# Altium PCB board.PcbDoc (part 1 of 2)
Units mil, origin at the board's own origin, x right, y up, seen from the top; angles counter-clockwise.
Board outline 3925 x 3925 mil, 2 copper layers (Top Layer, Bottom Layer); 233 components, 182 nets, 664 pads, 429 vias.
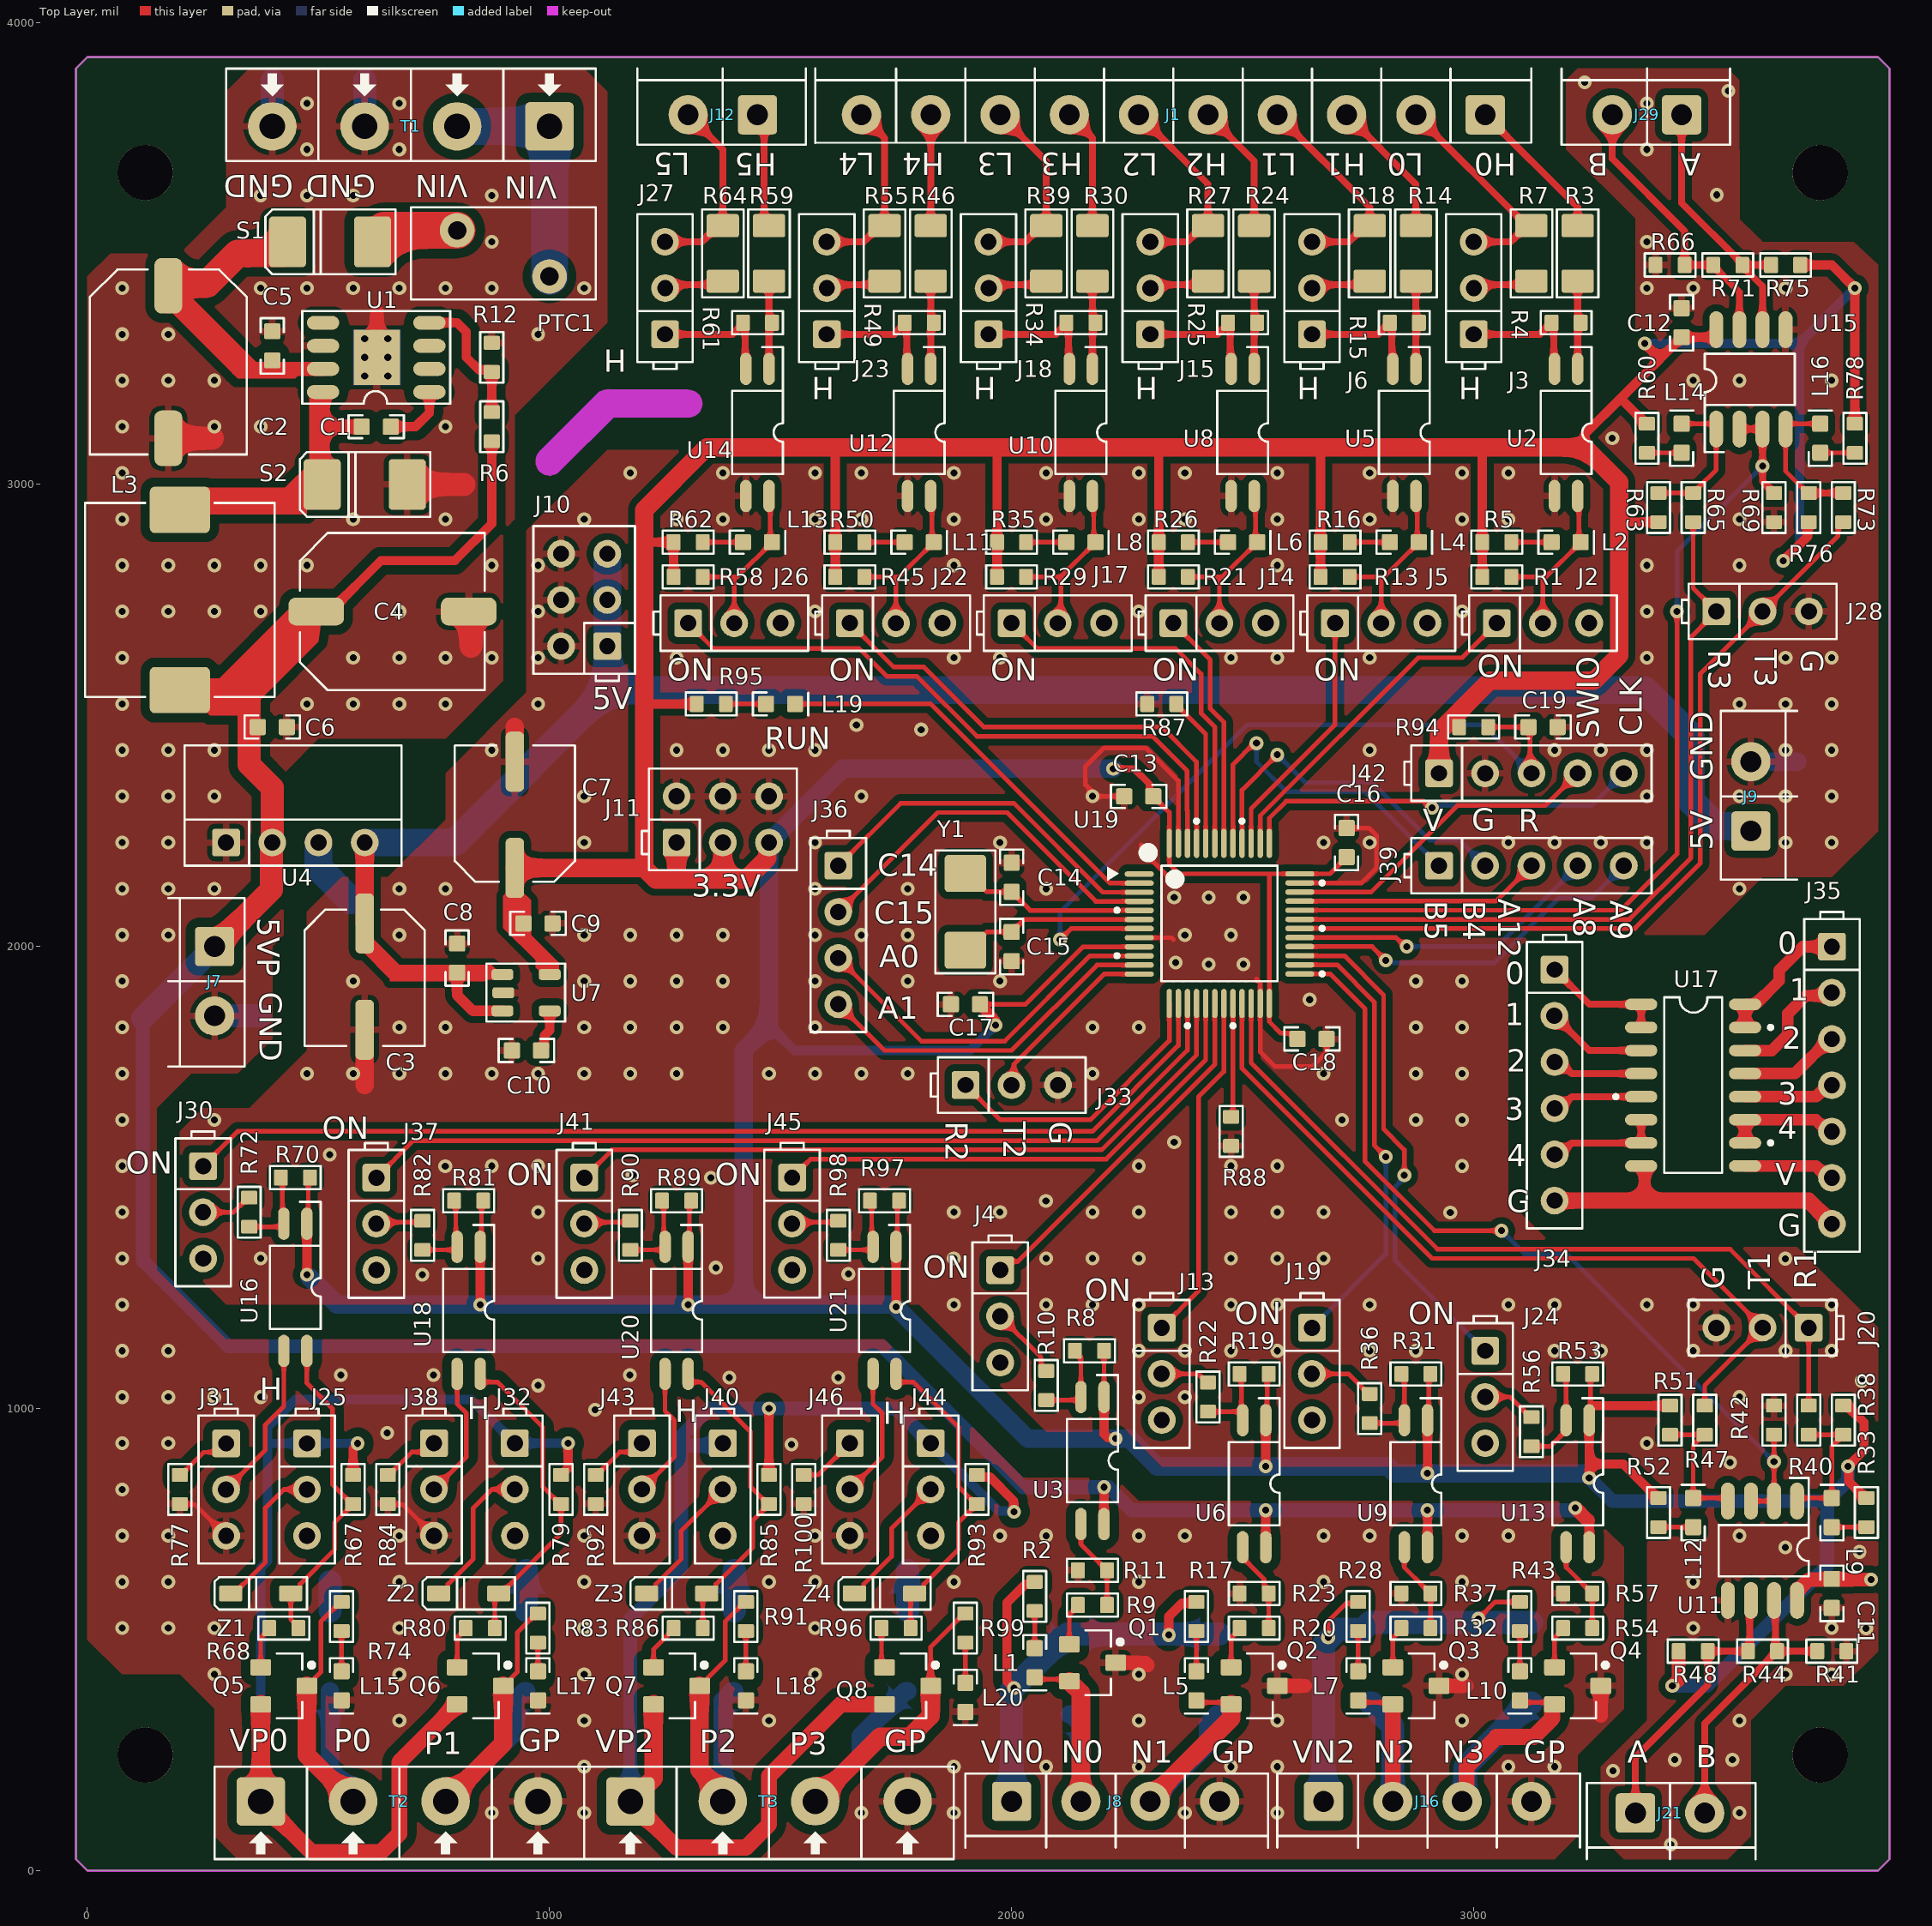
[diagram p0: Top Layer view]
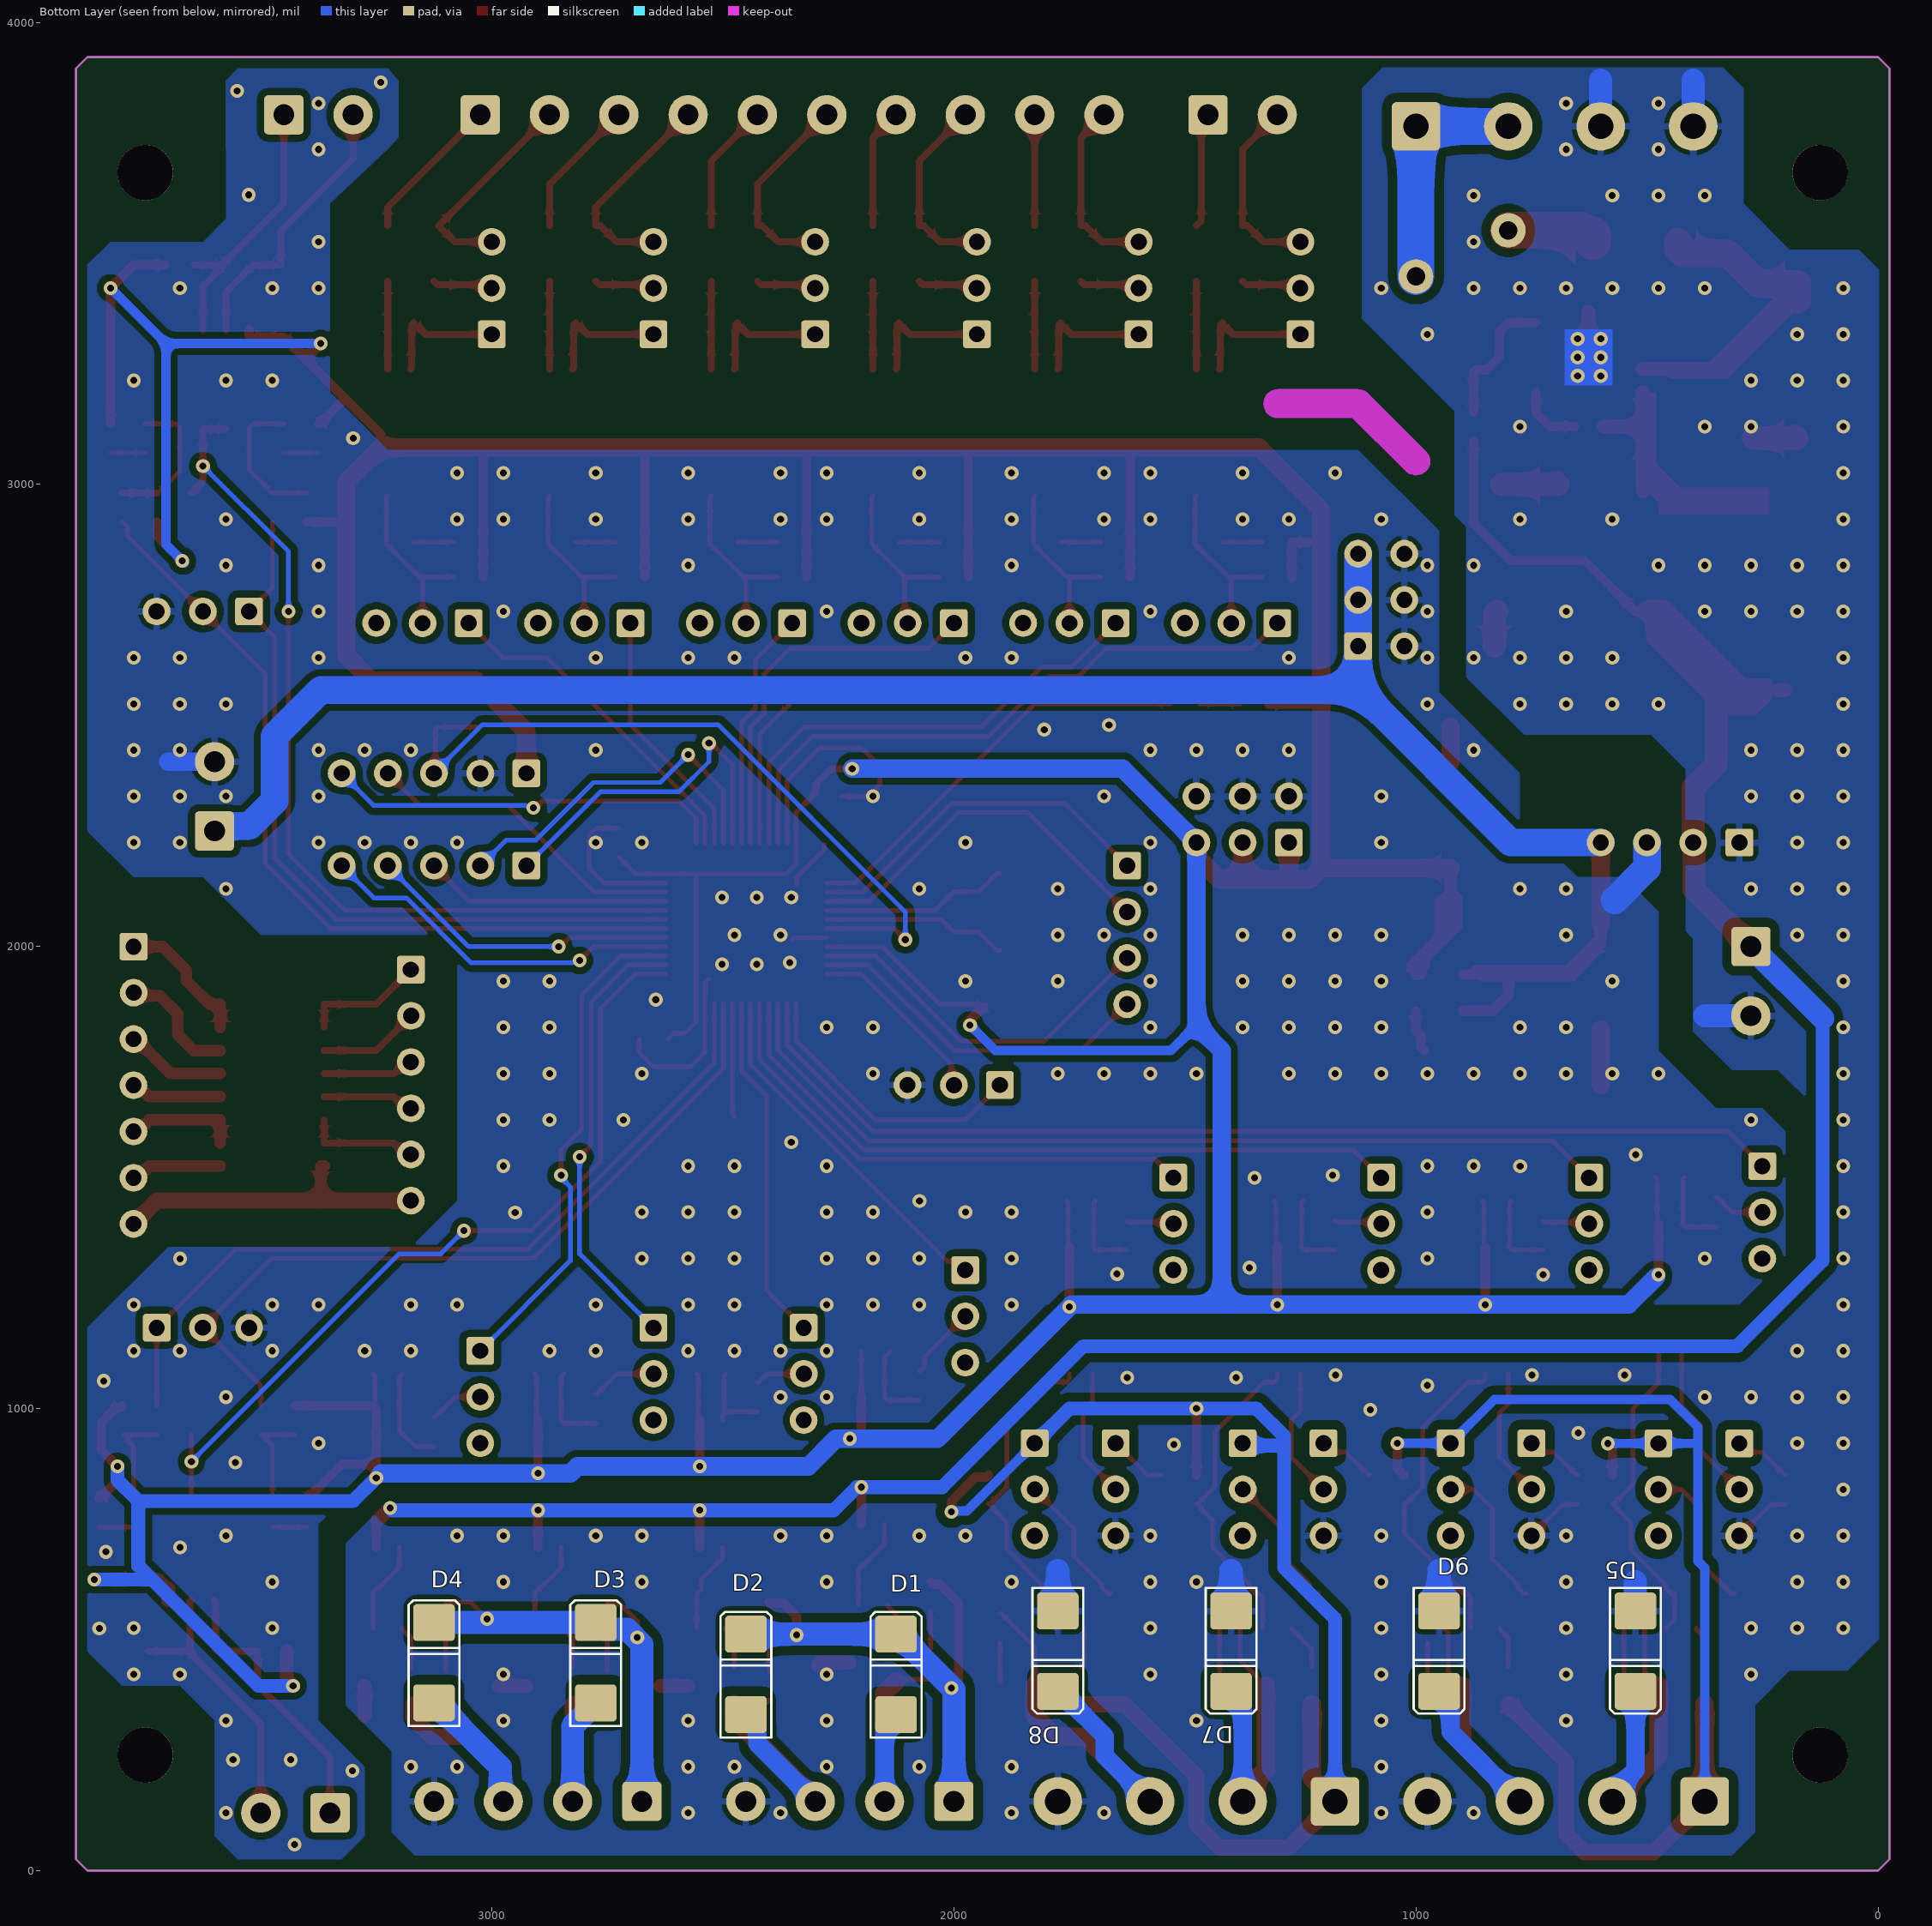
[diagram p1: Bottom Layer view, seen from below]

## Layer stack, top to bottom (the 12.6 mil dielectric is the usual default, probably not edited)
Top Solder: solder mask 0.4, Solder Resist, Dk 3.5
Top Layer: signal copper 1.4
Dielectric 1: dielectric 12.6, FR-4, Dk 4.8
Bottom Layer: signal copper 1.4
Bottom Solder: solder mask 0.4, Solder Resist, Dk 3.5

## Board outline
-25,25 0,0 3875,0 3900,25 3900,3900 3875,3925 0,3925 -25,3900
cut-out: 978.78,3071.22 ccw(c1000,3050) 1021.22,3028.78 1146.22,3153.78 ccw(c1125,3175) 1155.01,3175 ccw(c1125,3175) 1103.78,3196.22
cut-out: 1125,3144.98 cw(c1125,3175) 1125,3205.02 1300,3205.02 cw(c1300,3175) 1330.01,3175 cw(c1300,3175) 1300,3144.98

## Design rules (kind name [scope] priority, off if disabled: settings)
Clearance "Stitching GND" [IsStitchingVia and InNet('GND') vs (IsVia and (Not IsStitchingVia)) Or IsPad] p1: gap=5 ignorepadtopadclearanceinfootprint=FALSE
Clearance [InNamedPolygon('GND')] p2: gap=15 ignorepadtopadclearanceinfootprint=FALSE
Clearance "Stitching GP" [IsStitchingVia and InNet('GP') vs (IsVia and (Not IsStitchingVia)) Or IsPad] p3: gap=20 ignorepadtopadclearanceinfootprint=FALSE
Clearance Clearance_1 [InNamedPolygon('GP')] p4: gap=20 ignorepadtopadclearanceinfootprint=FALSE
Clearance Clearance_net [All] p5: gap=7 ignorepadtopadclearanceinfootprint=FALSE
HoleSize [All] p1: absolutevalues=TRUE maxlimit=150 minlimit=1 maxpercent=80.000 minpercent=20.000
HoleToHoleClearance [All] p1: gap=1 allowstackedmicrovias=TRUE
MinimumSolderMaskSliver [All] p1: minsoldermaskwidth=1
PlaneConnect [All] p1: planeconnectstyle=Relief reliefexpansion=20 reliefentries=4 reliefconductorwidth=15 reliefairgap=10
PolygonConnect PolygonConnect_1 [IsVia] p1: connectstyle=Direct reliefconductorwidth=10 reliefentries=4 polygonreliefangle="90 Angle" airgapwidth=10
PolygonConnect [All] p2: connectstyle=Relief reliefconductorwidth=15 reliefentries=4 polygonreliefangle="90 Angle" airgapwidth=10
RoutingVias [All] p1: holewidth=15 width=30 viastyle="Through Hole" minholewidth=15 minwidth=30 maxholewidth=20 maxwidth=40
SilkToSilkClearance [All] p1: silktosilkclearance=1
SilkToSolderMaskClearance [IsPad] p1: minsilkscreentomaskgap=1 clearancetoexposedcopper=TRUE
SolderMaskExpansion [All] p1: expansion=4 istentingtop=FALSE
Width [All] p1: maxlimit=100 minlimit=10 preferedwidth=30
24 further rules are at their usual default settings.

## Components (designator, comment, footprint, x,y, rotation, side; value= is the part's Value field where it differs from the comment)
C1 "10nF" "Capacitor 0603" 625,3125 r0 top value=10u
C2 "220uF/35V" "Capacitor ALU 8x10mm" 175,3100 r90 top
C3 "220uF/10V" "Capacitor ALU 6.3x7.7mm" 600,1820 r90 top
C4 "470uF/16V" "Capacitor ALU 8x10mm" 825,2725 r180 top
C5 "10nF/50V" "Capacitor 0603" 400,3300 r270 top value=10u
C6 "100nF" "Capacitor 0603" 400,2475 r180 top value=10u
C7 "220uF/10V" "Capacitor ALU 6.3x7.7mm" 925,2400 r270 top
C8 "100nF" "Capacitor 0603" 800,1975 r270 top value=10u
C9 "100nF" "Capacitor 0603" 975,2050 r180 top value=10u
C10 "22nF" "Capacitor 0603" 950,1775 r0 top value=10u
C11 "100nF" "CAPACITOR 0603" 3775,600 r90 top value=10u
C12 "100nF" "Capacitor 0603" 3450,3350 r270 top value=10u
C13 "100nF" "Capacitor 0603" 2275,2325 r180 top value=10u
C14 "22p" "Capacitor 0603" 2000,2150 r270 top value=10u
C15 "22p" "Capacitor 0603" 2000,2000 r90 top value=10u
C16 "100nF" "Capacitor 0603" 2725,2225 r270 top value=10u
C17 "100nF" "Capacitor 0603" 1900,1875 r0 top value=10u
C18 "100nF" "Capacitor 0603" 2650,1800 r0 top value=10u
C19 "100n" "Capacitor 0603" 3150,2475 r180 top value=10u
D1 "=value" "DIODE SS24 SMA" 2125,425 r90 bottom
D2 "=value" "DIODE SS24 SMA" 2450,425 r90 bottom
D3 "=value" "DIODE SS24 SMA" 2775,450 r90 bottom
D4 "=value" "DIODE SS24 SMA" 3125,450 r90 bottom
D5 "=value" "DIODE SS24 SMA" 525,475 r270 bottom
D6 "=value" "DIODE SS24 SMA" 950,475 r270 bottom
D7 "=value" "DIODE SS24 SMA" 1400,475 r270 bottom
D8 "=value" "DIODE SS24 SMA" 1775,475 r270 bottom
J1 "15EDG3.8 10P RA" "15EDG3.81 10P RA" 3025,3800 r180 top
J2 "jump 2.54mm 3p" "JUMP 2.54MM 3P" 3050,2700 r0 top
J3 "jump 2.54mm 3p" "JUMP 2.54MM 3P" 3000,3325 r90 top
J4 "jump 2.54mm 3p" "JUMP 2.54MM 3P" 1975.28,1299.69 r270 top
J5 "jump 2.54mm 3p" "JUMP 2.54MM 3P" 2700,2700 r0 top
J6 "jump 2.54mm 3p" "JUMP 2.54MM 3P" 2650,3325 r90 top
J7 "15EDG3.81 2P RA" "15EDG3.81 2P RA" 275,2000 r270 top
J8 "15EDG3.81 4P RA" "15EDG3.81 4P RA" 2000,150 r0 top
J9 "15EDG3.81 2P RA" "15EDG3.81 2P RA" 3600,2250 r90 top
J10 "jump 2.54mm 2x3p" "JUMP 2.54MM 2X3P" 1125,2650 r90 top
J11 "jump 2.54mm 2x3p" "JUMP 2.54MM 2X3P" 1275,2225 r0 top
J12 "15EDG3.81 2P RA" "15EDG3.81 2P RA" 1450,3800 r180 top
J13 "jump 2.54mm 3p" "JUMP 2.54MM 3P" 2325,1175 r270 top
J14 "jump 2.54mm 3p" "JUMP 2.54MM 3P" 2350,2700 r0 top
J15 "jump 2.54mm 3p" "JUMP 2.54MM 3P" 2300,3325 r90 top
J16 "15EDG3.81 4P RA" "15EDG3.81 4P RA" 2675,150 r0 top
J17 "jump 2.54mm 3p" "JUMP 2.54MM 3P" 2000,2700 r0 top
J18 "jump 2.54mm 3p" "JUMP 2.54MM 3P" 1950,3325 r90 top
J19 "jump 2.54mm 3p" "JUMP 2.54MM 3P" 2650,1175 r270 top
J20 "jump 2.54mm 3p" "JUMP 2.54MM 3P" 3725,1175 r180 top
J21 "15EDG3.81 2P RA" "15EDG3.81 2P RA" 3350,125 r0 top
J22 "jump 2.54mm 3p" "JUMP 2.54MM 3P" 1650,2700 r0 top
J23 "jump 2.54mm 3p" "JUMP 2.54MM 3P" 1600,3325 r90 top
J24 "jump 2.54mm 3p" "JUMP 2.54MM 3P" 3025,1125 r270 top
J25 "jump 2.54mm 3p" "JUMP 2.54MM 3P" 475.28,924.69 r270 top
J26 "jump 2.54mm 3p" "JUMP 2.54MM 3P" 1300,2700 r0 top
J27 "jump 2.54mm 3p" "JUMP 2.54MM 3P" 1250,3325 r90 top
J28 "jump 2.54mm 3p" "JUMP 2.54MM 3P" 3525.31,2725.28 r0 top
J29 "15EDG3.81 2P RA" "15EDG3.81 2P RA" 3450,3800 r180 top
J30 "jump 2.54mm 3p" "JUMP 2.54MM 3P" 250.28,1524.69 r270 top
J31 "jump 2.54mm 3p" "JUMP 2.54MM 3P" 300.28,924.69 r270 top
J32 "jump 2.54mm 3p" "JUMP 2.54MM 3P" 925,925 r270 top
J33 "jump 2.54mm 3p" "JUMP 2.54MM 3P" 1900.31,1700.28 r0 top
J34 "jump 2.54mm 6p" "JUMP 2.54MM 6P" 3175,1950 r270 top
J35 "jump 2.54mm 7p" "JUMP 2.54MM 7P" 3775.28,1999.69 r270 top
J36 "jump 2.54mm 4p" "JUMP 2.54MM 4P" 1625,2175 r270 top
J37 "jump 2.54mm 3p" "JUMP 2.54MM 3P" 625.28,1499.69 r270 top
J38 "jump 2.54mm 3p" "JUMP 2.54MM 3P" 750,925 r270 top
J39 "jump 2.54mm 5p" "JUMP 2.54MM 5P" 2925,2175 r0 top
J40 "jump 2.54mm 3p" "JUMP 2.54MM 3P" 1375,925 r270 top
J41 "jump 2.54mm 3p" "JUMP 2.54MM 3P" 1075.28,1499.69 r270 top
J42 "jump 2.54mm 5p" "JUMP 2.54MM 5P" 2925,2375 r0 top
J43 "jump 2.54mm 3p" "JUMP 2.54MM 3P" 1200,925 r270 top
J44 "jump 2.54mm 3p" "JUMP 2.54MM 3P" 1825,925 r270 top
J45 "jump 2.54mm 3p" "JUMP 2.54MM 3P" 1525,1500 r270 top
J46 "jump 2.54mm 3p" "JUMP 2.54MM 3P" 1650,925 r270 top
L1 "LED" "LED GREEN 0603 SMD" 2050,450 r270 top
L2 "LED" "LED RED 0603 SMD" 3200,2875 r0 top
L3 "33uH" "INDUCTOR SMD 10x10x4mm" 200,2750 r270 top
L4 "LED" "LED RED 0603 SMD" 2850,2875 r0 top
L5 "LED" "LED GREEN 0603 SMD" 2400,400 r270 top
L6 "LED" "LED RED 0603 SMD" 2500,2875 r0 top
L7 "LED" "LED GREEN 0603 SMD" 2750,400 r270 top
L8 "LED" "LED RED 0603 SMD" 2150,2875 r0 top
L9 "LED" "LED RED 0603 SMD" 3775,775 r90 top
L10 "LED" "LED GREEN 0603 SMD" 3100,400 r270 top
L11 "LED" "LED RED 0603 SMD" 1800,2875 r0 top
L12 "LED" "LED GREEN 0603 SMD" 3475,775 r90 top
L13 "LED" "LED RED 0603 SMD" 1450,2875 r0 top
L14 "LED" "LED RED 0603 SMD" 3450,3100 r90 top
L15 "LED" "LED GREEN 0603 SMD" 550,400 r270 top
L16 "LED" "LED GREEN 0603 SMD" 3750,3100 r90 top
L17 "LED" "LED GREEN 0603 SMD" 975,400 r270 top
L18 "LED" "LED GREEN 0603 SMD" 1425,400 r270 top
L19 "LED" "LED RED 0603 SMD" 1500,2525 r0 top
L20 "LED" "LED GREEN 0603 SMD" 1900,375 r270 top
PTC1 "2A/30V" "PTC DIP" 1000,3450 r180 top value=10k
Q1 "MOSFET N" "AO3401 MOSFET P SOT23" 2175,450 r270 top
Q2 "MOSFET N" "AO3401 MOSFET P SOT23" 2525,400 r270 top
Q3 "MOSFET N" "AO3401 MOSFET P SOT23" 2875,400 r270 top
Q4 "MOSFET N" "AO3401 MOSFET P SOT23" 3225,400 r270 top
Q5 "MOSFET P" "AO3401 MOSFET P SOT23" 425,400 r270 top
Q6 "MOSFET P" "AO3401 MOSFET P SOT23" 850,400 r270 top
Q7 "MOSFET P" "AO3401 MOSFET P SOT23" 1275,400 r270 top
Q8 "MOSFET P" "AO3401 MOSFET P SOT23" 1775,400 r270 top
R1 "4k7" "RES 0603" 3050,2800 r0 top
R2 "10k" "RES 0603" 2050,593.5 r270 top
R3 "1K" "RESISTOR 1206" 3225,3500 r270 top
R4 "47k" "RES 0603" 3200,3350 r180 top
R5 "4k7" "RES 0603" 3050,2875 r0 top
R6 "10k" "RES 0603" 875,3125 r270 top
R7 "1K" "RESISTOR 1206" 3125,3500 r270 top
R8 "47k" "RES 0603" 2168.5,1125 r0 top
R9 "100" "RES 0603" 2175,575 r0 top
R10 "1k" "RES 0603" 2075,1050 r270 top
R11 "4k7" "RES 0603" 2175,650 r0 top
R12 "3k3" "RES 0603" 875,3275 r270 top
R13 "4k7" "RES 0603" 2700,2800 r0 top
R14 "1K" "RESISTOR 1206" 2875,3500 r270 top
R15 "47k" "RES 0603" 2850,3350 r180 top
R16 "4k7" "RES 0603" 2700,2875 r0 top
R17 "4k7" "RES 0603" 2400,550 r270 top
R18 "1K" "RESISTOR 1206" 2775,3500 r270 top
R19 "47k" "RES 0603" 2525,1075 r0 top
R20 "100" "RES 0603" 2525,525 r0 top
R21 "4k7" "RES 0603" 2350,2800 r0 top
R22 "1k" "RES 0603" 2425,1025 r270 top
R23 "4k7" "RES 0603" 2525,600 r0 top
R24 "1K" "RESISTOR 1206" 2525,3500 r270 top
R25 "47k" "RES 0603" 2500,3350 r180 top
R26 "4k7" "RES 0603" 2350,2875 r0 top
R27 "1K" "RESISTOR 1206" 2425,3500 r270 top
R28 "4k7" "RES 0603" 2750,550 r270 top
R29 "4k7" "RES 0603" 2000,2800 r0 top
R30 "1K" "RESISTOR 1206" 2175,3500 r270 top
R31 "47k" "RES 0603" 2875,1075 r0 top
R32 "100" "RES 0603" 2875,525 r0 top
R33 "4k7" "RES 0603" 3850,775 r90 top
R34 "47k" "RES 0603" 2150,3350 r180 top
R35 "4k7" "RES 0603" 2000,2875 r0 top
R36 "1k" "RES 0603" 2775,1000 r270 top
R37 "4k7" "RES 0603" 2875,600 r0 top
R38 "4k7" "RES 0603" 3800,975 r90 top
R39 "1k" "RESISTOR 1206" 2075,3500 r270 top
R40 "100" "RES 0603" 3725,975 r270 top
R41 "4k7" "RES 0603" 3775,475 r0 top
R42 "4k7" "RES 0603" 3650,975 r270 top
R43 "4k7" "RES 0603" 3100,550 r270 top
R44 "4k7" "RES 0603" 3625,475 r0 top
R45 "4k7" "RES 0603" 1650,2800 r0 top
R46 "1K" "RESISTOR 1206" 1825,3500 r270 top
R47 "100" "RES 0603" 3500,975 r270 top
R48 "4k7" "RES 0603" 3475,475 r0 top
R49 "47k" "RES 0603" 1800,3350 r180 top
R50 "4k7" "RES 0603" 1650,2875 r0 top
R51 "4k7" "RES 0603" 3425,975 r90 top
R52 "4k7" "RES 0603" 3400,775 r90 top
R53 "47k" "RES 0603" 3225,1075 r0 top
R54 "100" "RES 0603" 3225,525 r0 top
R55 "1K" "RESISTOR 1206" 1725,3500 r270 top
R56 "1k" "RES 0603" 3125,950 r270 top
R57 "4k7" "RES 0603" 3225,600 r0 top
R58 "4k7" "RES 0603" 1300,2800 r0 top
R59 "1K" "RESISTOR 1206" 1475,3500 r270 top
R60 "4k7" "RES 0603" 3375,3100 r90 top
R61 "47k" "RES 0603" 1450,3350 r180 top
R62 "4k7" "RES 0603" 1300,2875 r0 top
R63 "4k7" "RES 0603" 3400,2950 r270 top
R64 "1K" "RESISTOR 1206" 1375,3500 r270 top
R65 "100" "RES 0603" 3475,2950 r90 top
R66 "4k7" "RES 0603" 3425,3475 r180 top
R67 "10k" "RES 0603" 575,825 r90 top
R68 "100" "RES 0603" 425,525 r0 top
R69 "4k7" "RES 0603" 3650,2950 r90 top
R70 "47k" "RES 0603" 450,1500 r0 top
R71 "4k7" "RES 0603" 3550,3475 r180 top
R72 "1k" "RES 0603" 350,1425 r270 top
R73 "100" "RES 0603" 3800,2950 r90 top
R74 "10k" "RES 0603" 550,550 r270 top
R75 "4k7" "RES 0603" 3675,3475 r180 top
R76 "4k7" "RES 0603" 3725,2950 r270 top
R77 "10k" "RES 0603" 200,825 r90 top
R78 "4k7" "RES 0603" 3825,3100 r90 top
R79 "10k" "RES 0603" 1025,825 r90 top
R80 "100" "RES 0603" 850,525 r0 top
R81 "47k" "RES 0603" 825,1450 r0 top
R82 "1k" "RES 0603" 725,1375 r270 top
R83 "10k" "RES 0603" 975,525 r270 top
R84 "10k" "RES 0603" 650,825 r90 top
R85 "10k" "RES 0603" 1475,825 r90 top
R86 "100" "RES 0603" 1300,525 r0 top
R87 "47k" "RES 0603" 2325,2525 r0 top
R88 "47k" "RES 0603" 2475,1600 r270 top
R89 "47k" "RES 0603" 1275,1450 r0 top
R90 "1k" "RES 0603" 1175,1375 r270 top
R91 "10k" "RES 0603" 1425,550 r270 top
R92 "10k" "RES 0603" 1100,825 r90 top
R93 "10k" "RES 0603" 1925,825 r90 top
R94 "10k" "RES 0603" 3000,2475 r180 top
R95 "4k7" "RES 0603" 1350,2525 r0 top
R96 "100" "RES 0603" 1750,525 r0 top
R97 "47k" "RES 0603" 1725,1450 r0 top
R98 "1k" "RES 0603" 1625,1375 r270 top
R99 "10k" "RES 0603" 1900,525 r270 top
R100 "10k" "RES 0603" 1550,825 r90 top
S1 "40V/3A" "DIODE SS24 SMB" 525,3525 r180 top
S2 "40V/3A" "DIODE SS24 SMB" 600,3000 r180 top
T1 "=value" "2EDG5.08 4P RA" 1000,3775 r180 top
T2 "=value" "2EDG5.08 4P RA" 375,150 r0 top
T3 "=value" "2EDG5.08 4P RA" 1175,150 r0 top
U1 "TPS5430" "SOP8 - PAD - VIA" 625,3275 r180 top
U2 "EL3H7" SSOP4 3225,3250 r270 top
U3 "EL3H7" SSOP4 2200,1025 r270 top
U4 "B0505S" B0505S 300,2225 r0 top
U5 "EL3H7" SSOP4 2875,3250 r270 top
U6 "EL3H7" SSOP4 2550,975 r270 top
U7 "RT9193-33GB" RT9193 988.59,1777.95 r0 top
U8 "EL3H7" SSOP4 2525,3250 r270 top
U9 "EL3H7" SSOP4 2900,975 r270 top
U10 "EL3H7" SSOP4 2175,3250 r270 top
U11 "MAX485" SOP8 3625,695 r270 top
U12 "EL3H7" SSOP4 1825,3250 r270 top
U13 "EL3H7" SSOP4 3250,975 r270 top
U14 "EL3H7" SSOP4 1475,3250 r270 top
U15 "MAX485" SOP8 3600,3225 r90 top
U16 "EL3H7" SSOP4 475,1400 r270 top
U17 "ULN2003" SOP16 3475,1700 r0 top
U18 "EL3H7" SSOP4 850,1350 r270 top
U19 "STM32F103C8T6" LQFP48 2450,2050 r0 top
U20 "EL3H7" SSOP4 1300,1350 r270 top
U21 "EL3H7" SSOP4 1750,1350 r270 top
Y1 "=Value" "Crystal SMD 5032" 1900,2075 r90 top
Z1 "BZT52C3V3" "DIODE SOD-123" 375,600 r180 top
Z2 "BZT52C3V3" "DIODE SOD-123" 825,600 r180 top
Z3 "BZT52C3V3" "DIODE SOD-123" 1275,600 r180 top
Z4 "BZT52C3V3" "DIODE SOD-123" 1725,600 r180 top

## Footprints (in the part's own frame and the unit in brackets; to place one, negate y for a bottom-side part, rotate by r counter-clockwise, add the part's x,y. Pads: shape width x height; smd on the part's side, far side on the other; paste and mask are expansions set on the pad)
"2EDG5.08 4P RA" [mil]
  rrect20% 105x105 hole 55: 1(0,0)
  round 105 hole 55: 2(200,0) 3(400,0) 4(600,0)
  silkscreen extent -100,-125 700,75, body extent -100,-411 700,65, height 331
"15EDG3.81 2P RA" [mil]
  rrect20% 85x85 hole 45: 1(0,0)
  round 85 hole 45: 2(150,0)
  silkscreen extent -105,-100 260,65, body extent -100,-671 255,54, height 360
"15EDG3.81 4P RA" [mil]
  rrect20% 85x85 hole 45: 1(0,0)
  round 85 hole 45: 2(150,0) 3(300,0) 4(450,0)
  silkscreen extent -100,-100 555,60, body extent -102,-674 552,50, height 315
"15EDG3.81 10P RA" [mil]
  rrect20% 85x85 hole 45: 1(0,0)
  round 85 hole 45: 2(150,0) 3(300,0) 4(450,0) 5(600,0) 6(750,0) 7(900,0) 8(1050,0) 9(1200,0) 10(1350,0)
  silkscreen extent -100,-100 1450,61, body extent -102,-674 1452,50, height 350
"AO3401 MOSFET P SOT23" [mil]
  rrect20% 35x45 smd: 1(40,-50) 2(0,50) 3(-40,-50)
  silkscreen extent -70,-15 70,65, body extent -59,-49 59,49, height 42
B0505S [mil] "Connector; Header; 4 Position"
  rrect20% 60x60 hole 35 mask+4: 1(0,0)
  round 60 hole 35: 2(100,0) 3(200,0) 4(300,0)
  silkscreen extent -90,-50 380,210, body extent -83,-40 373,200, height 500
"Capacitor 0603" [mil] "Capacitor 0603"
  rrect20% 35x35 smd: 1(-31.49,0.01) 2(31.51,0.01)
  silkscreen extent -60,-25 60,25, body extent -31,-16 32,16, height 31
"CAPACITOR 0603" [mil] "Capacitor 0603"
  rrect20% 35x35 smd: 1(-31.49,0.01) 2(31.51,0.01)
  silkscreen extent -60,-25 60,25, body extent -31,-16 32,16, height 31
"Capacitor ALU 6.3x7.7mm" [mil]
  rrect50% 130x40 smd: 1(0,0) 2(230,0)
  silkscreen extent -35,-130 260,130, body extent -35,-130 265,130, height 335
"Capacitor ALU 8x10mm" [mil]
  rrect50% 120x60 smd: 1(0,0) 2(330,0)
  silkscreen extent -35,-170 365,170, body extent -26,-167 356,167, height 426
"Crystal SMD 5032" [mil] "SMD 5032"
  rrect20% 80x90 smd: 1(-83,0) 2(83,0)
  silkscreen extent -133,-65 133,65, body extent -98,-63 98,63, height 55
"DIODE SOD-123" [mil] "diode sod-123"
  rrect20% 50x35 smd: 1(-65,0) 2(65,0)
  silkscreen extent -100,-35 100,35, body extent -73,-31 73,32, height 50
"DIODE SS24 SMA" [mil] "diode sma"
  rrect20% 80x90 smd: 1(-87,0) 2(87,0)
  silkscreen extent -137,-55 135,55, body extent -102,-51 102,51, height 94
"DIODE SS24 SMB" [mil] "diode smb"
  rrect20% 80x110 smd: 1(-92,0) 2(92,0)
  silkscreen extent -142,-70 140,70, body extent -107,-70 107,70, height 91
"INDUCTOR SMD 10x10x4mm" [mil] "Capacitor 0603"
  rrect20% 100x130 smd: 1(-195,0) 2(195,0)
  silkscreen extent -210,-205 210,205, body extent -205,-201 205,201, height 201
"JUMP 2.54MM 2X3P" [mil] "Connector; Jump; 6 Position"
  rrect20% 60x60 hole 35: 1(0,0)
  round 60 hole 35: 2(0,100) 3(100,0) 4(100,100) 5(200,0) 6(200,100)
  silkscreen extent -75,-60 260,160, body extent -50,-50 250,150, height 276
"JUMP 2.54MM 3P" [mil] "Connector; jump; 3 Position"
  rrect20% 60x60 hole 35: 1(0,0)
  round 60 hole 35: 2(99.69,-0.28) 3(200,0)
  silkscreen extent -75,-60 260,60, body extent -50,-50 250,50, height 276
"JUMP 2.54MM 4P" [mil] "Connector; jump; 4 Position"
  rrect20% 60x60 hole 35: 1(0,0)
  round 60 hole 35: 2(100,0) 3(200,0) 4(300,0)
  silkscreen extent -75,-60 360,60, body extent -50,-50 350,50, height 276
"JUMP 2.54MM 5P" [mil] "Connector; jump; 5 Position"
  rrect20% 60x60 hole 35: 1(0,0)
  round 60 hole 35: 2(99.69,-0.28) 3(200,0) 4(300,0) 5(400,0)
  silkscreen extent -75,-60 460,60, body extent -50,-50 450,50, height 276
"JUMP 2.54MM 6P" [mil] "Connector; jump; 6 Position"
  rrect20% 60x60 hole 35: 1(0,0)
  round 60 hole 35: 2(99.69,-0.28) 3(200,0) 4(300,0) 5(400,0) 6(500,0)
  silkscreen extent -75,-60 560,60, body extent -50,-50 550,50, height 276
"JUMP 2.54MM 7P" [mil] "Connector; jump; 7 Position"
  rrect20% 60x60 hole 35: 1(0,0)
  round 60 hole 35: 2(99.69,-0.28) 3(200,0) 4(300,0) 5(400,0) 6(500,0) 7(600,0)
  silkscreen extent -75,-60 660,60, body extent -50,-50 650,50, height 276
"LED GREEN 0603 SMD" [mil]
  rrect20% 35x35 smd: 1(-31.49,0) 2(31.5,0)
  silkscreen extent -60,-25 60,25, body extent -31,-16 32,16, height 24
"LED RED 0603 SMD" [mil]
  rrect20% 35x35 smd: 1(-31.5,0) 2(31.49,0)
  silkscreen extent -60,-25 60,25, body extent -32,-16 31,16, height 28
LQFP48 [mm] "LFQP48"
  oval 1.6x0.3 smd: 1(-4.413,2.715) 2(-4.413,2.215) 3(-4.413,1.715) 4(-4.413,1.215) 5(-4.413,0.715) 6(-4.413,0.215) 7(-4.413,-0.285) 8(-4.413,-0.785) 9(-4.413,-1.285) 10(-4.413,-1.785) 11(-4.413,-2.285) 12(-4.413,-2.785) 25(4.413,-2.775) 26(4.413,-2.275) 27(4.413,-1.775) 28(4.413,-1.275) 29(4.413,-0.775) 30(4.413,-0.275) 31(4.413,0.225) 32(4.413,0.725) 33(4.413,1.225) 34(4.413,1.725) 35(4.413,2.225) 36(4.413,2.725)
  oval 0.3x1.6 smd: 13(-2.763,-4.4) 14(-2.263,-4.4) 15(-1.763,-4.4) 16(-1.263,-4.4) 17(-0.762,-4.4) 18(-0.262,-4.4) 19(0.238,-4.4) 20(0.738,-4.4) 21(1.238,-4.4) 22(1.738,-4.4) 23(2.238,-4.4) 24(2.738,-4.4) 37(2.737,4.4) 38(2.237,4.4) 39(1.737,4.4) 40(1.237,4.4) 41(0.737,4.4) 42(0.237,4.4) 43(-0.263,4.4) 44(-0.763,4.4) 45(-1.263,4.4) 46(-1.763,4.4) 47(-2.263,4.4) 48(-2.763,4.4)
  silkscreen extent -6.16,-5.72 5.74,5.72, body extent -4.51,-4.53 4.5,4.48, height 1.46
"PTC DIP" [mil] "varistor"
  round 75 hole 40: 1(0,0) 2(200,-100)
  silkscreen extent -100,-150 300,50, body extent -101,-109 301,9, height 618
"RES 0603" [mil] "res 0603"
  rrect20% 30x35 smd: 1(-31.5,0) 2(31.5,0)
  silkscreen extent -55,-25 55,25, body extent -31,-17 31,17, height 19
"RESISTOR 1206" [mil]
  rrect20% 50x70 smd: 1(-60,0) 2(60,0)
  silkscreen extent -95,-45 95,45, body extent -63,-33 63,33, height 21
RT9193 [mm]
  rrect50% 1.2x0.6 smd: 1(-2.3,4.1) 2(-2.25,3.1) 3(-2.3,2.1) 4(0.3,2.1) 5(0.3,4.1)
  silkscreen extent -3.17,1.52 1.14,4.7, body extent -2.25,1.6 0.25,4.6, height 1.06
SOP8 [mil]
  oval 80x30 smd: 1(-105,75) 2(-105,25) 3(-105,-25) 4(-105,-75) 5(110,-75) 6(110,-25) 7(110,25) 8(110,75)
  silkscreen extent -155,-95 58,100, body extent -115,-95 121,98, height 62
"SOP8 - PAD - VIA" [mil]
  oval 70x30 smd: 1(-115,75) 2(-115,25) 3(-115,-25) 4(-115,-75) 5(115,-75) 6(115,-25) 7(115,25) 8(115,75)
  rect 100x120 smd: 9(-1.25,0)
  Bottom Layer region: -52.5,60 50,60 50,-60 -52.5,-60
  silkscreen extent -160,-100 160,100, body extent -118,-100 118,97, height 101
SOP16 [mil]
  oval 70x25 smd: 1(-112.5,175) 2(-112.5,125) 3(-112.5,75) 4(-112.5,25) 5(-112.5,-25) 6(-112.5,-75) 7(-112.5,-125) 8(-112.5,-175) 9(112.5,-175) 10(112.5,-125) 11(112.5,-75) 12(112.5,-25) 13(112.5,25) 14(112.5,75) 15(112.5,125) 16(112.5,175)
  silkscreen extent -171,-190 172,190, body extent -117,-197 115,196, height 57
SSOP4 [mil]
  oval 70x25 smd: 1(0,0) 2(0,-50) 3(275,-50) 4(275,0)
  silkscreen extent -48,-80 228,30, body extent 2,-76 278,30, height 79

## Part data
C1 C5 C6 C8 C9 C10 C11 C12 C13 C14 C15 C16 C17 C18 C19: library part "Capacitor 0603"
C2 C4: library part "capacitor aluminum smd 8x10mm"
C3 C7: library part "capacitor aluminum smd 6.3x7.7mm"
D1 D2 D3 D4 D5 D6 D7 D8: library part "diode SMA"
L1 L5 L7 L10 L12 L15 L16 L17 L18 L20: library part "LED GREEN SMD"
L2 L4 L6 L8 L9 L11 L13 L14 L19: library part "LED RED SMD"
L3: library part "INDUCTOR SMD 10x10x4mm"
PTC1: library part "PTC DIP"
Q1 Q2 Q3 Q4: library part "MOSFET N AO3402"
Q5 Q6 Q7 Q8: library part "MOSFET P AO3401"
R1 R2 R4 R5 R6 R8 R9 R10 R11 R12 R13 R15 R16 R17 R19 R20 R21 R22 R23 R25 R26 R28 R29 R31 R32 R33 R34 R35 R36 R37 R38 R40 R41 R42 R43 R44 R45 R47 R48 R49 R50 R51 R52 R53 R54 R56 R57 R58 R60 R61 R62 R63 R65 R66 R67 R68 R69 R70 R71 R72 R73 R74 R75 R76 R77 R78 R79 R80 R81 R82 R83 R84 R85 R86 R87 R88 R89 R90 R91 R92 R93 R94 R95 R96 R97 R98 R99 R100: library part res
R3 R7 R14 R18 R24 R27 R30 R39 R46 R55 R59 R64: library part "resistor 1206"
S1 S2: library part "diode SMB"
T1 T2 T3: library part "2EDG5.08 4P RA"
Y1: library part "Crystal 8MHZ SMD 5032"
Z1 Z2 Z3 Z4: library part "diode Zenner BZT52C3V3 SOD-123"

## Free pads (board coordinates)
  round 120 hole 120: 3(125,250) 3(125,3675) 3(3750,250) 3(3750,3675)

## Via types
v1: diameter 30, hole 15, Top Layer to Bottom Layer, tented both sides, 423 vias
v2: diameter 30/30 (per signal layer), hole 15, Top Layer to Bottom Layer, tented both sides, 6 vias

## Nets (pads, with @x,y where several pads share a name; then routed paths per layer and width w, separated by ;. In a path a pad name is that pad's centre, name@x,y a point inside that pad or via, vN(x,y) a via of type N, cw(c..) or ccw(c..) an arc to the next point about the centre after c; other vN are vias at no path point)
5V: C3.2 C8.2 J9.1 J10.1 J10.3 J10.5 U4.4 U7.1 U7.3 | length 4346
  Top Layer w23: C3.2@600,2050 600,2005 665.63,1939.37 C8.2@800.01,1939.37 ; C8.2@800.01,1943.49 C8.2@800.01,1939.37 ; U7.3@898.03,1860.63 834.37,1860.63 800.01,1894.99 C8.2@800.01,1939.37 ; U7.1@898.03,1939.37 C8.2@800.01,1939.37
  Top Layer w40: C3.2@600,2050 U4.4@600,2225
  Bottom Layer w60: U4.4@600,2225 795,2225 1125,2555 ; J10.5@1125,2850 J10.3@1125,2750 J10.1@1125,2650 1125,2555 ; J9.1@3600,2250 3588.85,2261.15 3523.85,2261.15 3470,2315 3470,2455 3370,2555 1125,2555
5V-P: C4.2 C6.2 J7.1 L3.2 R6.2 U3.4 U4.2 U6.4 U9.4 U13.4 | length 5780.4
  Top Layer w20: C4.2@495,2725 525,2725 635,2835 795,2835 875,2915 R6.2@875,3093.5 ; U3.4@2200,750 v1(2200,830) ; U6.4@2550,700 v1(2550,780) ; U9.4@2900,700 v1(2900,780) ; 3247.5,757.5 3250,755 U13.4@3250,700
  Top Layer w30: L3.2@200,2555 L3.2@215,2555 ; C4.2@465,2710 480,2710 C4.2@495,2725 ; v1(3220,785) 3247.5,757.5
  Top Layer w50: J7.1@275,2000 398.09,2123.09 398.09,2223.09 U4.2@400,2225 400,2343.85 350,2393.85 350,2575 ; C4.2@460,2720 465,2725 C4.2@495,2725
  Bottom Layer w30: 120,1845 120,1320 305,1135 1720,1135 2025,830 v1(2200,830) 2210,830 2260,780 v1(2550,780) v1(2900,780) 3215,780 v1(3220,785)
  Bottom Layer w50: 120,1845 J7.1@275,2000
A0: J36.3 U19.10 | length 802.4
  Top Layer w10: J36.3@1625,1975 1805,1795 1985,1795 2169.72,1979.72 U19.10@2276.28,1979.72
A1: J36.4 U19.11 | length 769.3
  Top Layer w10: J36.4@1625,1875 1725,1775 2000,1775 2185.04,1960.04 U19.11@2276.28,1960.04
A8: J39.4 U19.29 | length 681.8
  Top Layer w10: U19.29@2623.72,2019.49 2832.06,2019.49 2851.55,2000 v1(2855,2000)
  Bottom Layer w10: v1(2855,2000) 3050,2000 J39.4@3225,2175
A9: J39.5 U19.28 | length 802.7
  Top Layer w10: U19.28@2623.72,1999.8 2780.2,1999.8 v1(2810,1970)
  Bottom Layer w10: v1(2810,1970) 2813.83,1966.17 2824.68,1966.17 2825.86,1965 3045,1965 3185,2105 3255,2105 J39.5@3325,2175
A12: J39.3 U19.33 | length 533.1
  Top Layer w10: U19.33@2623.72,2098.23 3048.23,2098.23 J39.3@3125,2175
A-485-1: J21.1 R44.1 R48.2 U11.6 | length 614.5
  Top Layer w15: J21.1@3350,125 3350,245 3506.5,401.5 R48.2@3506.5,475 R44.1@3593.5,475 3597.13,478.63 3597.13,582.13 U11.6@3600,585
A-485-2: J29.1 R71.1 R75.2 U15.6 | length 598
  Top Layer w15: J29.1@3450,3800 3450,3609 3581.5,3477.5 R71.1@3581.5,3475 ; U15.6@3625,3335 3625,3429 3581.5,3472.5 3584,3475 R75.2@3643.5,3475
B4: J39.2 U19.40 | length 772.6
  Top Layer w10: U19.40@2498.72,2223.23 2498.72,2338.72 v1(2575,2415)
  Bottom Layer w10: v1(2575,2415) 2635,2355 2780,2355 2905,2230 2969.4,2230 J39.2@3024.69,2174.72
B5: J39.1 U19.41 | length 769
  Top Layer w10: U19.41@2479.04,2223.23 2479.04,2394.04 2525,2440 v1(2530,2440)
  Bottom Layer w10: v1(2530,2440) 2530,2400 2595,2335 2765,2335 J39.1@2925,2175
B-485-1: J21.2 R41.1 R44.2 U11.7 | length 616
  Top Layer w15: J21.2@3500,125 3500,318.5 3646.5,465 3649,465 3656.5,472.5 R44.2@3656.5,475 ; U11.7@3650,585 3652.87,582.13 3652.87,478.63 R44.2@3656.5,475 ; R41.1@3743.5,475 R44.2@3656.5,475
B-485-2: J29.2 R66.1 R71.2 U15.7 | length 613.8
  Top Layer w15: J29.2@3300,3800 3300,3705 3456.5,3548.5 R66.1@3456.5,3475 3516,3475 3575,3416 U15.7@3575,3335
BOOT0: R87.2 U19.44 | length 328.7
  Top Layer w10: R87.2@2356.5,2525 2356.5,2522.5 2366.5,2512.5 2367.5,2512.5 2419.98,2460.02 U19.44@2419.98,2223.23
BOOT1: R88.1 U19.20 | length 246.9
  Top Layer w10: R88.1@2475,1631.5 2479.04,1635.53 U19.20@2479.04,1876.77
C14: J36.1 U19.3 | length 786.9
  Top Layer w10: J36.1@1625,2175 1760,2310 2005,2310 2197.48,2117.52 U19.3@2276.28,2117.52
C15: J36.2 U19.4 | length 819.9
  Top Layer w10: J36.2@1625,2075 1840,2290 1990,2290 2182.17,2097.83 U19.4@2276.28,2097.83
ENB-485-1: R69.2 U15.2 U15.3 U19.32 | length 1983.5
  Top Layer w10: U19.32@2623.72,2078.54 3318.54,2078.54 3440,2200 v1(3440,2725)
  Top Layer w15: U15.2@3575,3120 U15.3@3625,3120 v1(3625,3040) 3625,3006.5 3640,2991.5 3640,2989 3647.5,2981.5 R69.2@3650,2981.5
  Bottom Layer w10: v1(3440,2725) 3440,2855 v1(3625,3040)
ENB-485-3: R42.2 U11.2 U11.3 U19.25 | length 1850.4
  Top Layer w10: U19.25@2623.72,1940.75 2689.25,1940.75 2765,1865 2765,1535 2915,1385 v1(3060,1385) ; U11.3@3600,800 U11.2@3650,800 v1(3650,885) R42.2@3650,943.5
  Bottom Layer w10: v1(3060,1385) 3110,1335 3200,1335 v1(3650,885)
GND: C3.1 C7.1 C8.1 C9.1 C10.1 C11.1 C12.1 C13.2 C14.1 C15.1 C16.1 C17.1 C18.2 C19.1 J9.2 J10.2 J10.4 J10.6 J11.2 J11.4 J11.6 J20.3 J28.3 J33.3 J42.2 R41.2 R42.1 R66.2 R69.1 R87.1 R88.2 U2.3 U4.3 U5.3 U7.2 U8.3 U10.3 U11.5 U12.3 U14.3 U15.5 U19.8 U19.23 U19.35 U19.47 | length 1832
  Top Layer w10: C13.2@2243.49,2324.99 2185.01,2324.99 2160,2350 2160,2390 2200,2430 2290,2430 2360.92,2359.07 U19.47@2360.92,2223.23 ; U19.8@2276.28,2019.09 2345.91,2019.09 2350,2015 ; 2280,2220 2280,2210 2340,2150 2340,2135 ; 2530,1930 2538.09,1921.91 U19.23@2538.09,1876.77 2538.09,1771.91 2570,1740 2650,1740 2681.51,1771.51 C18.2@2681.51,1800.01 ; U19.35@2623.72,2137.6 2757.6,2137.6 2790,2170 2790,2240 2773.51,2256.49 C16.1@2725.01,2256.49
  Top Layer w40: 600,1700 C3.1@600,1820 ; C7.1@925,2400 925,2475
  Bottom Layer w40: J9.2@3600,2400 3700,2400
  Bottom Layer w60: U4.3@500,2225 500,2170 570,2100
  other v1: 3426.75,56.29 3575,125 3301.75,216.29 3435,240 3560,240 3575,325 3675,425 3775,425 3849.3,524.47 3475,525 3775,525 3475,625 3835,690 3674.3,699.47 3575,725 3555.07,883.37 3375,925 2275,1025 2375,1025 3575,1025 3840,1060 2275,1125 2375,1125 2475,1125 2575,1125 2775,1125 2875,1125 3175,1125 3275,1125 3475,1125 3675,1125 3775,1125 1875,1225 2075,1225 2175,1225 2275,1225 2475,1225 2575,1225 2775,1225 3075,1225 3175,1225 3375,1225 3475,1225 3775,1225 725,1290 1646.75,1291.29 1360,1305 3674.3,1324.47 375,1325 975,1325 1875,1325 2075,1325 2175,1325 2275,1325 2475,1325 2575,1325 2675,1325 2949.3,1424.47 975,1425 1875,1425 1975,1425 2175,1425 2275,1425 2475,1425 2575,1425 2675,1425 2074.3,1449.47 1349.3,1499.47 1180,1505 774.3,1524.47 875,1525 975,1525 2275,1525 2475,1525 2575,1525 2975,1525 524.3,1549.47 2351.75,1576.29 275,1625 2715,1625 2875,1625 2975,1625 475,1725 575,1725 675,1725 775,1725 875,1725 975,1725 1075,1725 1175,1725 1275,1725 1475,1725 1575,1725 1675,1725 1775,1725 2175,1725 2675,1725 2875,1725 2975,1725 675,1825 775,1825 1075,1825 1175,1825 1275,1825 1375,1825 1575,1825 2175,1825 2275,1825 2875,1825 2975,1825 2645,1885 575,1925 1075,1925 1175,1925 1275,1925 1375,1925 1575,1925 1775,1925 1975,1925 2875,1925 2975,1925 2426.75,1961.29 2501.75,1961.29 2355,1965 675,2025 1075,2025 1175,2025 1275,2025 1375,2025 1575,2025 1675,2025 1775,2025 2375,2025 2475,2025 2351.75,2106.29 2426.75,2106.29 2501.75,2106.29 675,2125 775,2125 1575,2125 1775,2125 2075,2125 3575,2125 1075,2225 1575,2225 1975,2225 2675,2225 2775,2225 3075,2225 3175,2225 3275,2225 3375,2225 3675,2225 3775,2225 1075,2325 1675,2325 2175,2325 3375,2325 3575,2325 3675,2325 3775,2325 875,2425 1275,2425 1375,2425 1475,2425 1575,2425 2775,2425 3175,2425 3275,2425 3375,2425 3675,2425 3775,2425 1804.3,2469.47 1664.3,2479.47 975,2525 3575,2525 3675,2525 3775,2525 975,2625 1275,2625 1875,2625 1975,2625 2475,2625 2575,2625 2775,2625 3375,2625 3675,2625 3775,2625 975,2725 1575,2725 2275,2725 2975,2725 3375,2725 975,2825 1875,2825 2575,2825 3375,2825 3575,2825 1075,2925 1275,2925 1375,2925 1575,2925 1675,2925 1875,2925 2075,2925 2275,2925 2375,2925 2575,2925 2775,2925 2975,2925 3075,2925 3575,2925 1175,3025 1375,3025 1575,3025 1675,3025 1875,3025 2075,3025 2275,3025 2375,3025 2575,3025 2775,3025 2975,3025 3075,3025 3300,3100 3475,3225 3575,3225 3775,3225 3375,3425 3475,3425 3675,3425 3375,3525 3526.07,3626.66 3375,3725 3375,3825 3551.07,3851.66 3240,3870
GNDP: C2.1 C4.1 C5.1 C6.1 D5.1 D6.1 D7.1 D8.1 J7.2 J8.4 J16.4 J31.3 J38.3 J43.3 J46.3 L15.2 L17.2 L18.2 L20.2 Q1.2 Q2.2 Q3.2 Q4.2 R11.1 R12.1 R23.1 R37.1 R57.1 R77.1 R84.1 R92.1 R100.1 S2.1 T1.3 T1.4 T2.4 T3.4 U1.6 U1.9 U4.1 | length 1549.2
  Top Layer w10: R77.1@200,793.5 201.03,792.47 232.5,792.47 J31.3@300.28,724.69 ; R84.1@650,793.5 651,792.5 682.5,792.5 J38.3@750,725
  Top Layer w30: U1.9@626.25,3275 626.25,3373.75 ; Q1.2@2225,450 2290,450 2295,445 ; Q2.2@2575,400 2635,400 ; Q3.2@2925,400 2985,400 ; 3275,335 Q4.2@3275,400
  Top Layer w50: C2.1@180,3105 C2.1@175,3100 270,3100 ; S2.1@697,3005 S2.1@692,3000 815,3000 ; C4.1@825,2725 830,2720 830,2650
  Bottom Layer w50: J7.2@275,1850 375,1850 ; T1.4@400,3775 400,3875 ; D5.1@525,562 525,625 ; T1.3@600,3775 600,3875 ; D6.1@950,562 950,650 ; D7.1@1400,562 1400,650 ; D8.1@1775,562 1775,650
  other v1: 875,125 1075,125 1675,125 1875,125 2375,125 2575,125 1075,225 1875,225 2075,225 2275,225 2475,225 2575,225 3075,225 3175,225 675,325 1075,325 1475,325 2275,325 2575,325 2975,325 275,425 675,425 1075,425 1575,425 2275,425 2975,425 75,525 175,525 275,525 675,525 1075,525 1575,525 75,625 175,625 675,625 1075,625 1475,625 1575,625 1875,625 2275,625 2675,625 2975,625 75,725 175,725 675,725 1075,725 1575,725 1975,725 2075,725 2275,725 2375,725 2675,725 2775,725 2975,725 3075,725 75,825 1523.65,922.37 75,925 175,925 648.65,947.37 1098.65,997.37 75,1025 175,1025 275,1025 375,1025 975,1050 1389.41,1066.8 1624.65,1066.8 548.65,1072.37 748.65,1072.37 1173.65,1072.37 75,1125 175,1125 75,1225 75,1325 75,1425 75,1525 75,1625 75,1725 75,1825 75,1925 75,2025 175,2025 75,2125 175,2125 275,2125 75,2225 175,2225 75,2325 175,2325 275,2325 75,2425 175,2425 275,2425 75,2525 475,2525 575,2525 675,2525 775,2525 75,2625 575,2625 675,2625 775,2625 875,2625 75,2725 175,2725 275,2725 375,2725 675,2725 75,2825 175,2825 275,2825 375,2825 475,2825 875,2825 75,2925 575,2925 775,2925 75,3025 75,3125 275,3125 375,3125 775,3125 75,3225 175,3225 275,3225 75,3325 175,3325 975,3325 75,3425 375,3425 475,3425 575,3425 675,3425 775,3425 875,3425 1075,3425 875,3525 375,3625 475,3625 575,3625 875,3625 475,3725 675,3725 475,3825 675,3825
  other v2: 600,3235 650,3235 600,3275 650,3275 600,3315 650,3315
GO: J34.6 J35.7 U17.8 | length 703.6
  Top Layer w25: U17.8@3362.5,1525 3370,1525 3370,1450
  Top Layer w35: J34.6@3175,1450 3370,1450 3724.97,1450 J35.7@3775.28,1399.69
IN-0: J2.2 L2.2 R1.2 U2.4 | length 383.9
  Top Layer w10: R1.2@3081.5,2800 3156.49,2800 ; J2.2@3149.69,2699.72 3149.69,2793.19 3156.49,2800 ; U2.4@3225,2975 3227.87,2972.13 3227.87,2871.38 3156.49,2800
IN-1: J5.2 L4.2 R13.2 U5.4 | length 381.2
  Top Layer w10: R13.2@2731.5,2800 2800,2800 ; J5.2@2799.69,2699.72 2799.69,2799.69 2800,2800 ; U5.4@2875,2975 2877.87,2972.13 2877.87,2871.38 2806.49,2800 2800,2800
IN-2: J14.2 L6.2 R21.2 U8.4 | length 381.2
  Top Layer w10: R21.2@2381.5,2800 2449.19,2800 ; J14.2@2449.69,2699.72 2449.69,2799.5 2449.19,2800 ; U8.4@2525,2975 2527.87,2972.13 2527.87,2871.38 2456.49,2800 2449.19,2800
IN-3: J17.2 L8.2 R29.2 U10.4 | length 383.9
  Top Layer w10: R29.2@2031.5,2800 2095,2800 2099.69,2800 2106.49,2800 ; J17.2@2099.69,2699.72 2106.49,2706.53 2106.49,2800 ; U10.4@2175,2975 2177.87,2972.13 2177.87,2871.38 2106.49,2800
IN-4: J22.2 L11.2 R45.2 U12.4 | length 381.2
  Top Layer w10: R45.2@1681.5,2800 1749.23,2800 ; J22.2@1749.69,2699.72 1749.69,2799.54 1749.23,2800 ; U12.4@1825,2975 1827.87,2972.13 1827.87,2871.38 1756.49,2800 1749.23,2800
IN-5: J26.2 L13.2 R58.2 U14.4 | length 386
  Top Layer w10: R58.2@1331.5,2800 1395,2800 ; J26.2@1399.69,2699.72 1399.69,2795.31 1395,2800 ; U14.4@1475,2975 1477.87,2972.13 1477.87,2878.62 L13.2@1481.49,2875 1406.49,2800 1395,2800
IN-H-0: J1.1 R3.1 | length 322.8
  Top Layer w15: J1.1@3025,3800 3225,3600 R3.1@3225,3560
IN-H-1: J1.3 R14.1 | length 302.1
  Top Layer w15: J1.3@2725,3800 2875,3650 R14.1@2875,3560
IN-H-2: J1.5 R24.1 | length 281.4
  Top Layer w15: J1.5@2425,3800 2525,3700 R24.1@2525,3560
IN-H-3: J1.7 R30.1 | length 260.7
  Top Layer w15: J1.7@2125,3800 2175,3750 R30.1@2175,3560
IN-H-4: J1.9 R46.1 | length 240
  Top Layer w15: R46.1@1825,3560 J1.9@1825,3800
IN-H-5: J12.1 R59.1 | length 250.4
  Top Layer w15: J12.1@1450,3800 1464.5,3785.5 1464.5,3570.5 R59.1@1475,3560
IN-L-0: J1.2 J3.3 R7.1 | length 468.9
  Top Layer w15: J1.2@2875,3800 3115,3560 3080,3525 J3.3@3000,3525
IN-L-1: J1.4 J6.3 R18.1 | length 462.3
  Top Layer w15: J1.4@2575,3800 2775,3600 R18.1@2775,3560 2765,3560 2730,3525 J6.3@2650,3525
IN-L-2: J1.6 J15.3 R27.1 | length 441.6
  Top Layer w15: J1.6@2275,3800 2425,3650 R27.1@2425,3560 2415,3560 2380,3525 J15.3@2300,3525
IN-L-3: J1.8 J18.3 R39.1 | length 420.9
  Top Layer w15: J18.3@1950,3525 2030,3525 2065,3560 R39.1@2075,3560 2075,3700 J1.8@1975,3800
IN-L-4: J1.10 J23.3 R55.1 | length 400.2
  Top Layer w15: J23.3@1600,3525 1680,3525 1715,3560 R55.1@1725,3560 1725,3750 J1.10@1675,3800
IN-L-5: J12.2 J27.3 R64.1 | length 410.6
  Top Layer w15: J27.3@1250,3525 1330,3525 1365,3560 R64.1@1375,3560 1375,3725 J12.2@1300,3800
INPUT-0: J2.1 U19.38 | length 744.5
  Top Layer w10: U19.38@2538.09,2223.23 2538.09,2283.09 2880,2625 2975,2625 J2.1@3050,2700
INPUT-1: J5.1 U19.39 | length 552
  Top Layer w10: U19.39@2518.41,2223.23 2518.41,2298.41 2700,2480 J5.1@2700,2700
INPUT-2: J14.1 U19.42 | length 522.1
  Top Layer w10: J14.1@2350,2700 2430,2620 2430,2515 2459.35,2485.65 U19.42@2459.35,2223.23
INPUT-3: J17.1 U19.43 | length 834.6
  Top Layer w10: J17.1@2000,2700 2055,2645 2355,2645 2410,2590 2410,2505 2439.67,2475.33 U19.43@2439.67,2223.23
INPUT-4: J22.1 U19.45 | length 1051.2
  Top Layer w10: J22.1@1650,2700 1745,2605 1810,2605 1940,2475 2325,2475 2400,2400 2400,2315 2400.3,2314.7 U19.45@2400.3,2223.23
